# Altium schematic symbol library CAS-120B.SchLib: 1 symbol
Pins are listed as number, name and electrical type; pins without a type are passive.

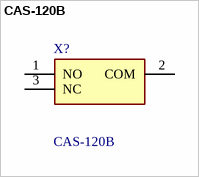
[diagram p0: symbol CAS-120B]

## CAS-120B
designator X?
SPDT, ON-ON  Slide, 100mA @ 6V DC Gull Wing SMD Terminal, Bulk Packaging, Washable with seal tape - Bulk; Manufacturer_Name: NIDEC COPAL; Geometry.Height: 2.5mm
footprint CAS120B
pins: 1 NO, 2 COM, 3 NC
